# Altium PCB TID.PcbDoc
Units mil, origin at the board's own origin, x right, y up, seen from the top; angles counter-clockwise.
Board outline 1000 x 1330 mil, 4 copper layers (Top Layer, InternalPlane1, MidLayer1, Bottom Layer), stack 88.8 mil thick; 24 components, 7 nets, 51 pads, 63 vias.
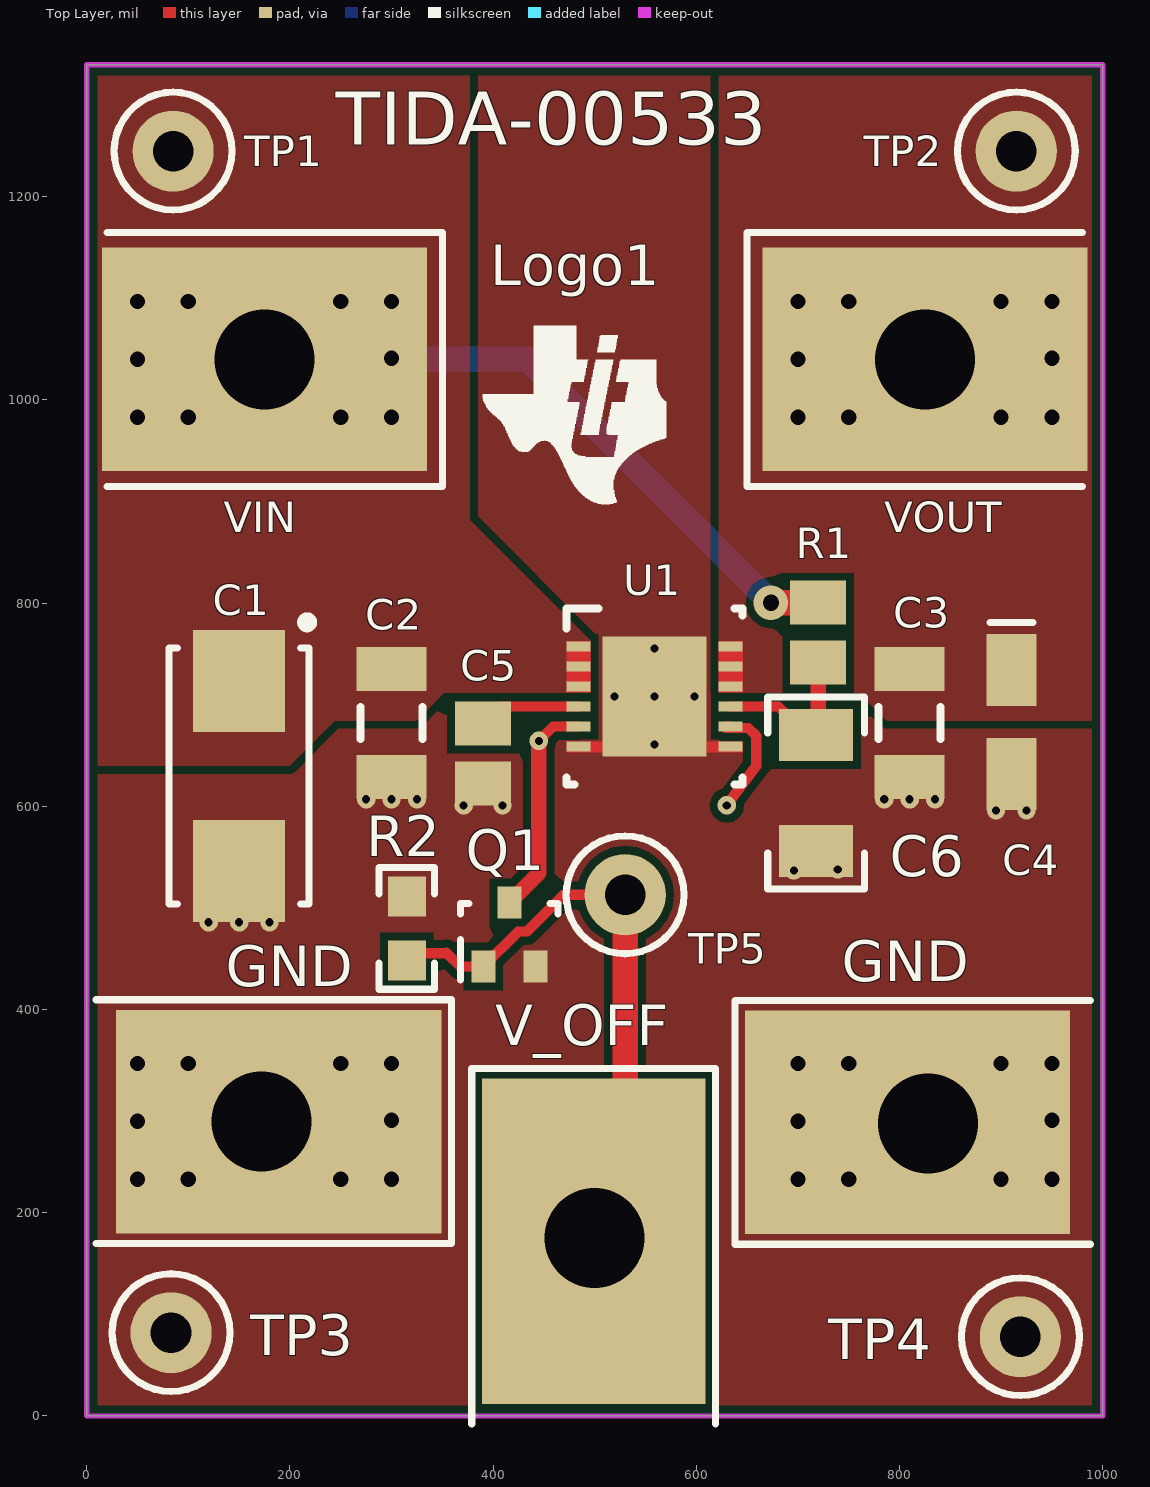
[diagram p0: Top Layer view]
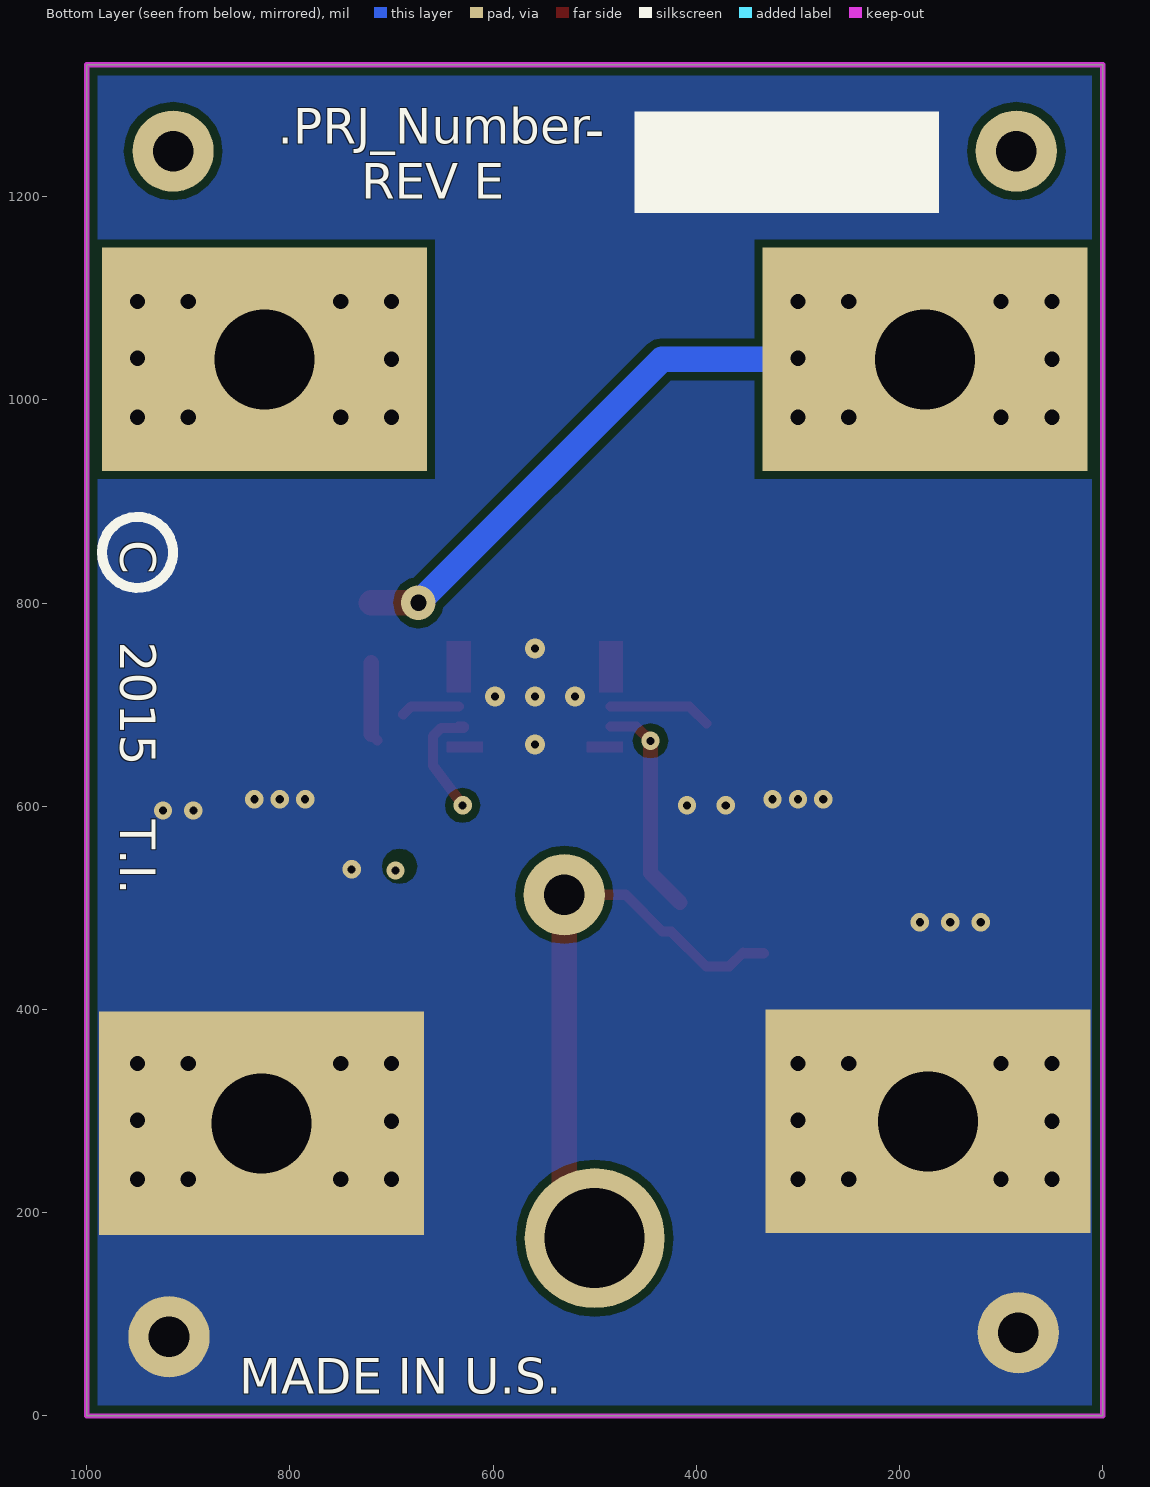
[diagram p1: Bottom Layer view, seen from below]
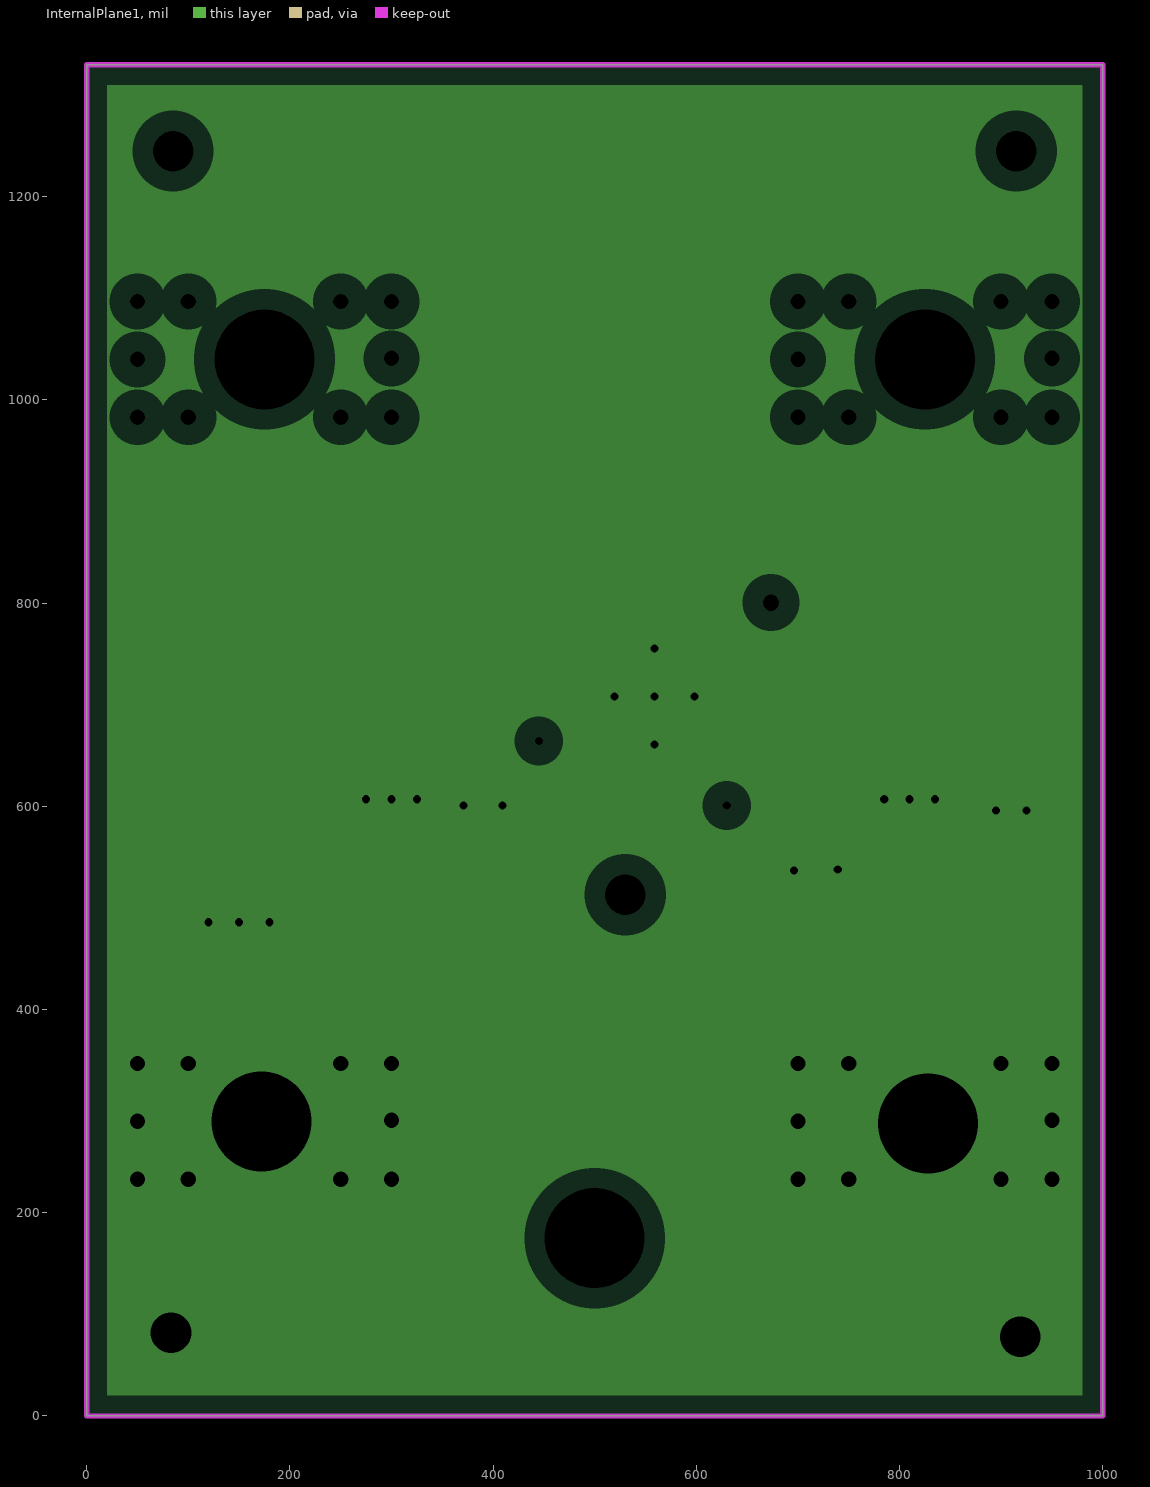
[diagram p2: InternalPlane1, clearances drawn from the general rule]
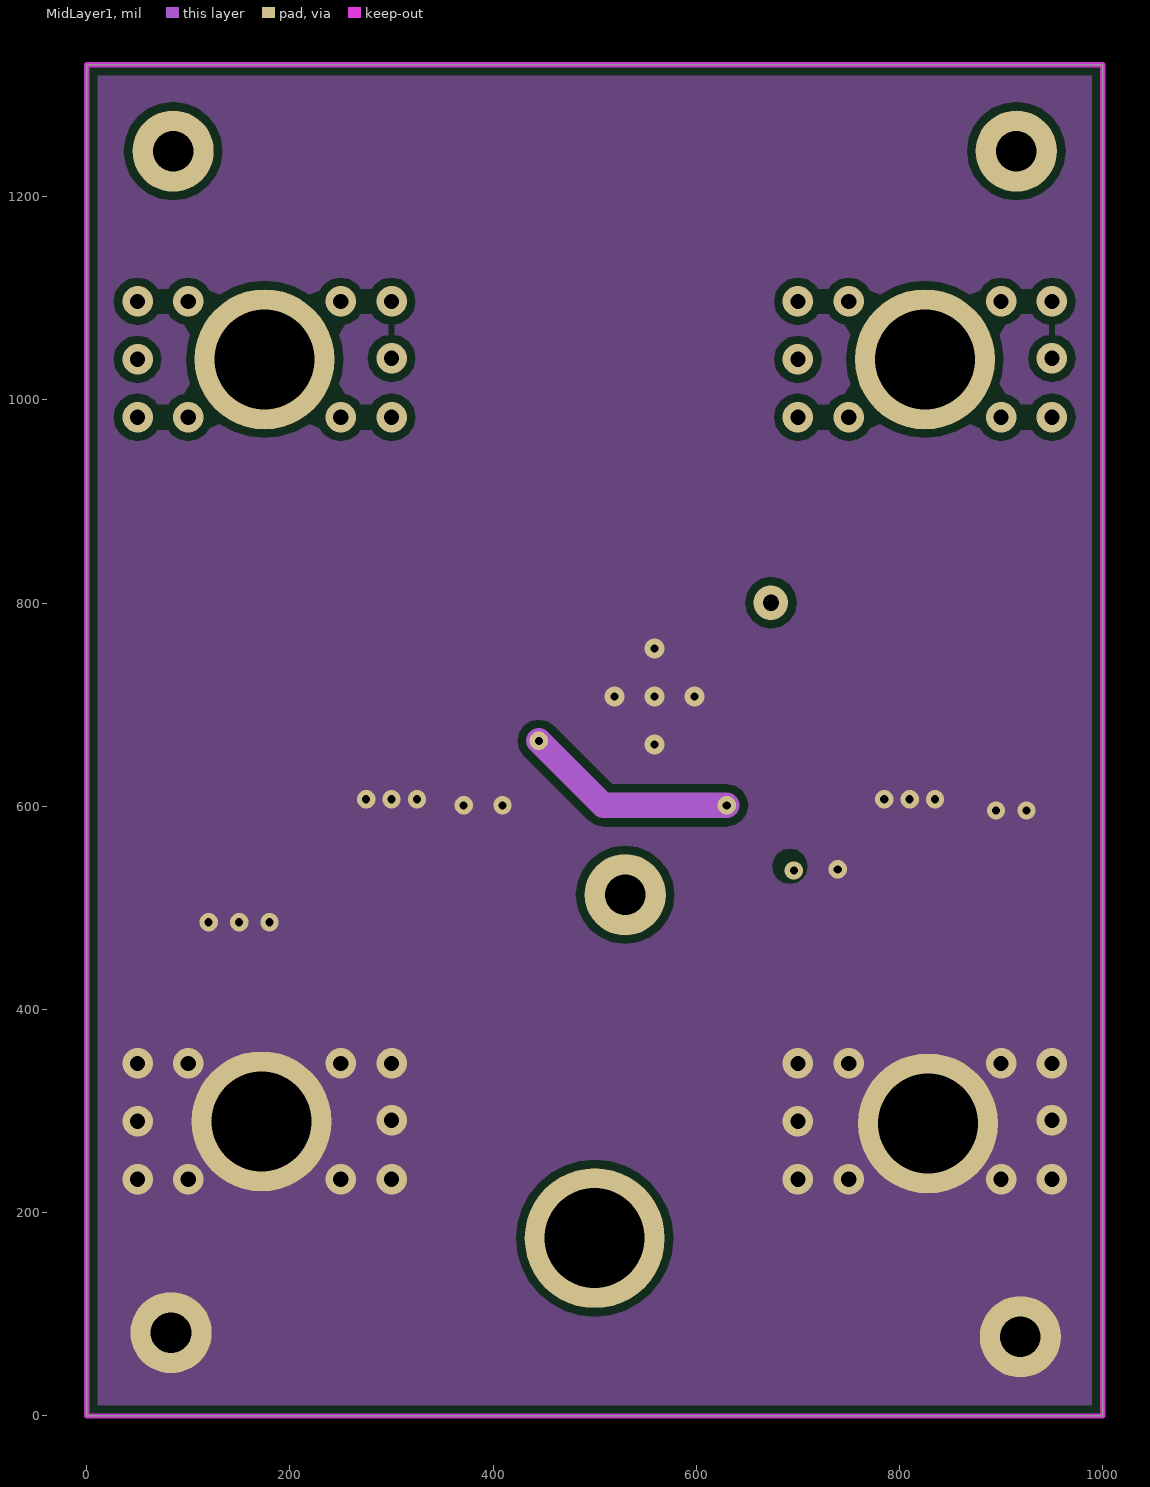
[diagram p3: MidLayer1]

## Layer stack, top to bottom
Top Solder: solder mask 0.4, Solder Resist, Dk 3.5
Top Layer: signal copper 1.4
Dielectric1: core 58, FR-4, Dk 4.8
InternalPlane1: plane copper 1.4, net GND
Dielectric3: prepreg 12.6, FR-4, Dk 4.8
MidLayer1: signal copper 1.4
Dielectric2: core 12.6, FR-4, Dk 4.8
Bottom Layer: signal copper 1.4
Bottom Solder: solder mask 0.4, Solder Resist, Dk 3.5

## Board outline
0,0 1000,0 1000,1330 0,1330

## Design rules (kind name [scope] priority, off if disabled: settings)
AcuteAngle [All] p1: minimum=4.50000000000000E+0001 checktracksonly=FALSE
AssemblyTestPointUsage [All] p1: valid=2
Clearance [All] p1: gap=8
ComponentClearance ComponentClearance_Logo [InComponentClass(Logo)] p1: gap=50 collisioncheckmode=3 verticalgap=10 showdistances=FALSE
ComponentClearance ComponentClearance_ScrewToNut [(HasFootprint('NY PMS 440 0025 PH')) vs (HasFootprint('Keystone_1902C'))] p2: gap=5 collisioncheckmode=3 verticalgap=10 showdistances=FALSE
ComponentClearance ComponentClearance_MountingHoles [InComponentClass('Mounting Holes')] p3: gap=150 collisioncheckmode=3 verticalgap=100000 showdistances=FALSE
ComponentClearance ComponentClearance_SmallPassives [HasFootprint('0201*') or HasFootprint('0402*') or HasFootprint('0508') or HasFootprint('0603*') or HasFootprint('0612') or HasFootprint('0805*') or HasFootprint('0815*') or HasFootprint('0830*') or HasFootprint('1206*') or HasFootprint('1210*') or HasFootprint('1808*') or HasFootprint('1812*') or HasFootprint('1825*') or HasFootprint('2010*') or HasFootprint('2220*') or HasFootprint('2225*') or HasFootprint('2512*') or HasFootprint('2728*') or HasFootprint('3518*') vs HasFootprint('0201*') or HasFootprint('0402*') or HasFootprint('0508') or HasFootprint('0603*') or HasFootprint('0612') or HasFootprint('0805*') or HasFootprint('0815*') or HasFootprint('0830*') or HasFootprint('1206*') or HasFootprint('1210*') or HasFootprint('1808*') or HasFootprint('1812*') or HasFootprint('1825*') or HasFootprint('2010*') or HasFootprint('2220*') or HasFootprint('2225*') or HasFootprint('2512*') or HasFootprint('2728*') or HasFootprint('3518*')] p4: gap=15 collisioncheckmode=3 verticalgap=10 showdistances=FALSE
ComponentClearance ComponentClearance_THtoSMT [IsThruComponent vs IsSMTComponent] p5: gap=20 collisioncheckmode=3 verticalgap=100000 showdistances=FALSE
ComponentClearance ComponentClearance_THtoTH [IsThruComponent vs IsThruComponent] p6: gap=100 collisioncheckmode=3 verticalgap=100000 showdistances=FALSE
ComponentClearance [All] p7: gap=20 collisioncheckmode=3 verticalgap=10 showdistances=FALSE
DiffPairsRouting [All] p1: maxlimit=100 minlimit=10 mostfreqgap=10 toplayer_minwidth=15 toplayer_maxwidth=15 toplayer_prefwidth=15 midlayer1_minwidth=15 midlayer1_maxwidth=15 midlayer1_prefwidth=15 bottomlayer_minwidth=15 bottomlayer_maxwidth=15 bottomlayer_prefwidth=15 maxuncoupledlength=1000
FabricationTestPointUsage TestPointUsage [All] p1: valid=2 allowmultiple=FALSE
FabricationTestpoint Testpoint [All] p1: side=3 testpointundercomponent=TRUE minsize=40 maxsize=100 preferedsize=60 minholesize=0 maxholesize=40 preferedholesize=32 testpointgrid=1 allowsidetop=TRUE allowsidebottom=TRUE usegrid=TRUE gridtolerance=0.01
FanoutControl Fanout_LCC [IsLCC] p1: bgadir=Out bgaviamode=Centered fanoutstyle=Auto fanoutdirection=Alternating viagrid=1 // Fanout_LCC (Default Rule)
FanoutControl Fanout_BGA [IsBGA] p2: bgadir=Out bgaviamode=Centered fanoutstyle=Auto fanoutdirection=Alternating viagrid=1 // Fanout_BGA (Default Rule)
FanoutControl Fanout_Default [All] p4: bgadir=Out bgaviamode=Centered fanoutstyle=Auto fanoutdirection=Alternating viagrid=1 // Fanout_Default (Default Rule)
FanoutControl Fanout_Small [(CompPinCount < 5)] p5: bgadir=Out bgaviamode=Centered fanoutstyle=Auto fanoutdirection=OutThenIn viagrid=1 // Fanout_Small (Default Rule)
HoleSize [All] p1: absolutevalues=TRUE maxlimit=251 minlimit=5 maxpercent=80.000 minpercent=20.000
MinimumAnnularRing [All] p1: minimumring=2
MinimumSolderMaskSliver [All] p1: minsoldermaskwidth=1
PlaneClearance [All] p1: clearance=20
PlaneConnect [All] p1: planeconnectstyle=Direct reliefexpansion=10 reliefentries=4 reliefconductorwidth=10 reliefairgap=10
PolygonConnect [All] p1: connectstyle=Direct reliefconductorwidth=10 reliefentries=4 polygonreliefangle="90 Angle" airgapwidth=10
RoutingLayers [All] p1: top layer_v5=TRUE mid layer 1_v5=FALSE bottom layer_v5=TRUE
RoutingVias [All] p1: holewidth=16 width=34 viastyle="Through Hole" minholewidth=8 minwidth=26 maxholewidth=40 maxwidth=65
SMDToCorner [All] p1: distance=0
SilkToSilkClearance [All] p1: silktosilkclearance=5
SilkToSolderMaskClearance SilkscreenOverComponentPads [IsPad] p1: minsilkscreentomaskgap=2 clearancetoexposedcopper=TRUE
SolderMaskExpansion [All] p1: expansion=3
UnpouredPolygon [All] p1: allowunpoured=FALSE
Width [All] p1: maxlimit=100 minlimit=6 preferedwidth=10 checkconnectedcopper=TRUE
13 further rules are at their usual default settings.

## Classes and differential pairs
component class BlankSheet: C1 C2 C3 C4 C5 C6 GND Q1 R1 R2 TP1 TP2 TP3 TP4 TP5 TP14 TP? U1 V_OFF VIN VOUT
component class Logo: Logo1
component class AssemblyNote: ZZ2 ZZ3 ZZ4
component class TID_Hardware: !PCB Logo1 ZZ2 ZZ3 ZZ4

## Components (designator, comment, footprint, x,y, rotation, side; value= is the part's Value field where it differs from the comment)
C1 "TPSC106K025R0500" 6032-28 150,630 r270 top
C2 "12103C105KAT2A" 1206L 300,682 r270 top
C3 "1206YC106KAT2A" 1206L 810,682 r270 top
C4 "TPSA106K010R0900" 3216-18 910,683 r270 top
C5 "08055C104KAT2A" 0805L 390,652 r270 top
C6 "GRM31CR71C106KAC7L" 1206 718,613 r270 top
GND "6092" 6092 993,289 r180 top
GND "6092" 6092 4,289.64 r0 top
Logo1 "Texas Instruments" TI_Symbol_Overlay_Small 480,985 r0 top
Q1 "2N7002KW" SOT-323 416,474 r90 top
R1 "CRCW080510K0FKEA" 0805L 720,771 r270 top
R2 "RC0603FR-07100KL" 0603 315,480 r270 top
TP1 "5000" Keystone5000 85,1245 r0 top
TP2 "5000" Keystone5000 915,1245 r0 top
TP3 "5001" Keystone5001 83,82 r0 top
TP4 "5001" Keystone5001 919,78 r0 top
TP5 "5002" Keystone5002 529.92,513 r0 top
U1 "LP38798SD-ADJ/NOPB" DNT0012B 559,708 r0 top
V_OFF "6091" 6091#1 499,-13 r90 top
VIN "6091" 6091#2 175,1040 r0 top
VOUT "6091" 6091#2 825,1040 r180 top
ZZ2 "These assemblies are ESD sensitive, ESD precautions shall be observed." AssemblyNote -721,2060 r0 top
ZZ3 "These assemblies must be clean and free from flux and all contaminants. Use of no clean flux is not acceptable." AssemblyNote -721,1693 r0 top
ZZ4 "These assemblies must comply with workmanship standards IPC-A-610 Class 2, unless otherwise specified." AssemblyNote -1048,1532 r0 top

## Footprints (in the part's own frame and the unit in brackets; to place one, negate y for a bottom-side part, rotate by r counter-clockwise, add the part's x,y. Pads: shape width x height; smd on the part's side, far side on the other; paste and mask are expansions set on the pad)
0603 [mm] "0603 from SM-752 data"
  rect 1x0.95 smd: 1(-0.8,0) 2(0.8,0)
  silkscreen extent -1.52,-0.69 1.52,0.69, body extent -0.87,-0.47 0.87,0.47, height 0.85
0805L [mm] "0805 from SM-752 data"
  rect 1.1x1.4 smd: 1(-0.75,0) 2(0.75,0)
  body extent -1.1,-0.72 1.1,0.72, height 1.1
1206 [mm] "1206 from SM-752 data"
  rect 1.3x1.85 smd: 1(-1.45,0) 2(1.45,0)
  silkscreen extent -2.4,-1.21 2.4,1.21, body extent -1.7,-0.9 1.7,0.9, height 1.35
1206L [mm] "1206 from SM-752 data"
  rect 1.1x1.75 smd: 1(-1.35,0) 2(1.35,0)
  silkscreen extent -0.4,-0.78 0.4,0.78, body extent -1.7,-0.9 1.7,0.9, height 1.35
3216-18 [mm] "Medium density IPC, based on Kemet T495 dimensions"
  rect 1.8x1.25 smd: 1(-1.3,0) 2(1.3,0)
  silkscreen extent -2.49,-0.54 -2.49,0.54, body extent -1.7,-0.9 1.7,0.9, height 1.8
6032-28 [mm] "Medium Density IPC based on Vishay Sprague 293D datasheet."
  rect 2.55x2.3 smd: 1(-2.375,0) 2(2.375,0)
  silkscreen extent -3.96,-1.75 3.2,1.83, body extent -3.15,-1.75 3.15,1.75, height 2.8
6091#1 [mil] "Keystone Insulated End Launch Banana Jack"
  rect 320x220 smd: 1(185,0)
  silkscreen extent 5,-120 355,120, body extent -666,-216 271,216, height 227
6091#2 [mil] "Keystone Insulated End Launch Banana Jack"
  rect 320x220 smd: 1(0,0)
  silkscreen extent -155,-125 175,125, body extent -846,-216 91,216, height 227
6092 [mil] "Keystone Insulated End Launch Banana Jack"
  rect 320x220 smd: 1(185,0)
  silkscreen extent 5,-120 355,120, body extent -666,-216 271,216, height 227
AssemblyNote [mil] "Assembly Note"
DNT0012B [mm] "SON, 12-Leads, Body 4x4mm, Pitch 0.5mm"
  rect 0.6x0.25 smd: 1(-1.9,1.25) 2(-1.9,0.75) 3(-1.9,0.25) 4(-1.9,-0.25) 5(-1.9,-0.75) 6(-1.9,-1.25) 7(1.9,-1.25) 8(1.9,-0.75) 9(1.9,-0.25) 10(1.9,0.25) 11(1.9,0.75) 12(1.9,1.25)
  rect 2.6x3 smd paste-1.3: 13(0,0)
  silkscreen extent -2.2,-2.2 2.2,2.2, body extent -2.05,-2.05 2.05,2.05, height 0.81
Keystone5000 [mil] "For Keystone 500x miniature loop terminals"
  round 80 hole 40: 1(0,0)
  silkscreen extent -58,-58 58,58, body extent -49,-49 49,49, height 182
Keystone5001 [mil] "For Keystone 500x miniature loop terminals"
  round 80 hole 40: 1(0,0)
  silkscreen extent -58,-58 58,58, body extent -49,-49 49,49, height 182
Keystone5002 [mil] "For Keystone 500x miniature loop terminals"
  round 80 hole 40: 1(0,0)
  silkscreen extent -58,-58 58,58, body extent -49,-49 49,49, height 182
SOT-323 [mm] "Zetex recommended land pattern.  March 2007"
  rect 0.8x0.6 smd: 1(-0.8,0.65) 2(-0.8,-0.65) 3(0.8,0)
  silkscreen extent -1.14,-1.22 0.77,1.22, body extent -1.13,-1.13 1.12,1.12, height 1.13
TI_Symbol_Overlay_Small [mil]
  silkscreen extent -90,-88 91,88

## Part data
C1: "CAP, TANT, 10uF, 25V, +/-10%, 0.5 ohm, 6032-28 SMD"
C2: library part 12063C105KAT2A, "CAP, MLCC, 1uF, 25V, +/-10%, X7R, 1206"
C3: library part C3216X5R1C106M, "CAP, MLCC, 10uF, 16V, +/-10%, X7R, 1206"
C4: "CAP, TANT, 10uF, 10V, +/-10%, 0.9 ohm, 3216-18 SMD"
C5: "CAP, CERM, 0.1uF, 50V, +/-10%, X7R, 0805"
C6: "CAP, CERM, 10 µF, 16 V, +/- 10%, X7R, 1206"
GND GND: "Standard Banana Jack, Insulated, Black"
Logo1: library part TI_Logo, "Texas Instrument Corporate Signature"
Q1: "MOSFET, N-CH, 60 V, 0.31 A, SOT-323"
R1: "RES, 10.0 k, 1%, 0.125 W, 0805"
R2: "RES, 100 k, 1%, 0.1 W, 0603"
TP1 TP2: "Test Point, TH, Miniature, Red"
TP3 TP4: "Test Point, Miniature, Black, TH"
TP5: "Test Point, TH, Miniature, White"
U1: "Ultra Low Noise, 800 mA Linear Voltage Regulator for RF/Analog Circuits, DNT0012B"
V_OFF VIN VOUT: "Standard Banana Jack, Insulated, Red"
ZZ2 ZZ3 ZZ4: library part AssemblyNote

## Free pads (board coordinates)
  round 137.79 hole 98.42: 0(175,1040) 0(825,1040) 1(500,175) 2(172,290) 3(828,288)
  rect 320x220 smd far side: GND(172,290) GND(828,288) VIN(175,1040) VOUT(825,1040)

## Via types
v1: diameter 30, hole 15, Top Layer to Bottom Layer, tented bottom, 40 vias
v2: diameter 18, hole 8, Top Layer to Bottom Layer, tented both sides, 15 vias
v3: diameter 19.68, hole 7.87, Top Layer to Bottom Layer, 5 vias
v4: diameter 18, hole 8, Top Layer to Bottom Layer, tented bottom, 2 vias
v5: diameter 34, hole 16, Top Layer to Bottom Layer, 1 vias

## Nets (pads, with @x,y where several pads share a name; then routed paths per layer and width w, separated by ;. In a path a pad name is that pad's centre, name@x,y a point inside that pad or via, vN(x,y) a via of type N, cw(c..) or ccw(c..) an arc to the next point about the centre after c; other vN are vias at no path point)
FB_EN: Q1.3 U1.5 U1.8 | length 544.9
  Top Layer w10: v4(445,664.47) 459,678.47 U1.5 ; v4(630,601) 659,640 659,669.38 651.38,677 628.88,677 628.88,678.47 U1.8
  Top Layer w15: Q1.3 445,534.5 v4(445,664.47)
  MidLayer1 w25: v4(445,664.47) 508.47,601 v4(630,601)
GND: C1.2 C2.2 C3.2 C4.2 C5.2 C6.2 GND.1 pad.2 pad.3 pad.GND Q1.2 R2.1 TP3.1 TP4.1 U1.6 U1.7 U1.13
  other v1: 50,233 100,233 250,233 300,233 700,233 750,233 900,233 950,233 50,290 700,290 300,291 950,291 50,347 100,347 250,347 300,347 700,347 750,347 900,347 950,347
  other v2: 120,486 150,486 180,486 696,537 739.24,538 895,596 925,596 371,601 409.25,601 275,607 300,607 325,607 785,607 810,607 835,607
  other v3: 559,660.76 519.63,708 559,708 598.37,708 559,755.24
NetC5_1: C5.1 U1.4 | length 101.1
  Top Layer w10: C5.1 406.63,698.16 U1.4
NetC6_1: C6.1 R1.2 U1.9 | length 136.6
  Top Layer w10: U1.9 680.93,698.16 C6.1@688.41,690.68 ; C6.1@714,665.09 C6.1@720,671.09
  Top Layer w15: C6.1@720,671.09 R1.2
V_OFF: pad.1 Q1.1 R2.2 TP5.1 V_OFF.1 | length 581.6
  Top Layer w10: 333.7,455.5 353.5,455.5 354,456 367.5,442.5 Q1.1 424.65,476.75 433.2,476.75 469.45,513 TP5.1 ; pad.1 pad.1@529.92,204.92
  Top Layer w25: pad.1@529.92,204.92 TP5.1
VIN: C1.1 C2.1 pad.0@175,1040 pad.VIN R1.1 TP1.1 U1.1 U1.2 U1.3 VIN.1 | length 644.2
  Top Layer w25: v5(673.47,800.53) R1.1
  Bottom Layer w25: pad.VIN 434,1040 v5(673.47,800.53)
  other v1: 50,983 100,983 250,983 300,983 50,1040 300,1041 50,1097 100,1097 250,1097 300,1097
VOUT: C3.1 C4.1 pad.0@825,1040 pad.VOUT TP2.1 U1.10 U1.11 U1.12 VOUT.1
  other v1: 700,983 750,983 900,983 950,983 700,1040 950,1041 700,1097 750,1097 900,1097 950,1097

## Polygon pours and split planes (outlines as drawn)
VOUT on Top Layer "Top Layer-No Net 1" (solid, pour order 4): 622,712 760,712 787.62,684.38 1000,684.38 1000,1330 622,1330
VIN on Top Layer "Top Layer-No Net" (solid, pour order 2): 496,712 352,712 324.38,684.38 244.38,684.38 200,640 0,640 0,1330 377,1329 377,882 496,763
GND on Top Layer "Top Layer-No Net 2" (solid, pour order 13): 0,0 1000,0 1000,1330 999,1328.97 0,1328.97 0,1330
GND on Bottom Layer "Bottom Layer-No Net" (solid, pour order 9): 0,0 1000,0 1000,1330 0,1330
GND on MidLayer1 "MidLayer1-No Net" (solid, pour order 11): 0,0 1000,0 1000,1330 0,1330
GND on InternalPlane1 (split plane): 979.9,20.1 20.1,20.1 20.1,1309.9 979.9,1309.9

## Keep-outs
Keep-Out Layer:
  the board outline again, w5
  text ".Layer_Name" at -1023,-1518.49 h60

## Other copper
Top Layer:
  rectangle net VOUT: 622,712 646,763
  rectangle net VIN: 472,712 496,763
  rectangle net GND: 610,653 646,664
  region net GND: 508,664 472,664 472,653 508,653
  text ".Layer_Name" at -1023,-1518.49 h60
Bottom Layer:
  text ".Layer_Name" at -1023,-1518.49 h60

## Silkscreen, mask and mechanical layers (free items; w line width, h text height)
Top Overlay:
  text "TIDA-00533" at 245,1234 h90
  text ".Layer_Name" at -1023,-1518.49 h60
Bottom Overlay:
  circle w10: c950,850 r35
  rectangle: 161,1184 461,1284
  text ".PRJ_Number" at 812,1252 h35
  text "-" at 490,1247 h40
  text "REV E" at 730,1198 h35
  text "C" at 967,862 h35 r90
  text "2015" at 967,762 h35 r90
  text "T.I." at 967,587 h35 r90
  text "MADE IN U.S." at 850,22 h35
  text ".Layer_Name" at -1023,-1518.49 h60
Top Paste:
  text ".Layer_Name" at -1023,-1518.49 h60
Bottom Paste:
  text ".Layer_Name" at -1023,-1518.49 h60
Top Solder:
  text ".Layer_Name" at -1023,-1518.49 h60
  text ".Layer_Name" at -1023,-1518.49 h60
Bottom Solder:
  text ".Layer_Name" at -1023,-1518.49 h60
Drill Guide:
  text ".Layer_Name" at -1023,-1518.49 h60
M1 Board Outline:
  the board outline again, w5
  text ".Layer_Name" at -1023,-1518.49 h60
M2 Board Dimensions:
  rectangle: -1600.5,-945.5 -1475.5,-820.5
  rectangle: -1475.5,-1070.5 -1100.5,-945.5
  lines w7: -1600.5,-945.5 -600.5,-945.5 ; -1475.5,-1070.5 -1475.5,-820.5 ; -1350.5,-1070.5 -1350.5,-820.5 ; -1100.5,-1070.5 -1100.5,-820.5 ; -850.5,-1070.5 -850.5,-820.5 ; -1600.5,-1070.5 -600.5,-1070.5 -600.5,-820.5 -1600.5,-820.5 -1600.5,-1070.5
  lines w10: -1600.5,-1135.5 -1600.5,-1115.5 ; -1540.5,-1145.5 -1600.5,-1125.5 ; -1540.5,-1105.5 -1600.5,-1125.5 ; -1376.42,-1125.5 -1600.5,-1125.5 ; -824.58,-1125.5 -600.5,-1125.5 ; -660.5,-1145.5 -600.5,-1125.5 ; -660.5,-1105.5 -600.5,-1125.5 ; -600.5,-1135.5 -600.5,-1115.5
  text "1000 (mil)" at -1366.42,-1161.49 h60
  text ".Layer_Name" at -1023,-1518.49 h60
M3 3D STEP Top:
  text ".Layer_Name" at -1023,-1518.49 h60
M4 3D STEP Bottom:
  text ".Layer_Name" at -1023,-1518.49 h60
M5 Assembly Top:
  lines w7: 7740,-623.5 8865,-623.5 ; 7740,-501 8862.5,-501 ; 8055,-743.5 8055,-381 ; 8440,-743.5 7740,-743.5 ; 8440,-381 7740,-381 ; 7740,-743.5 8865,-743.5 8865,-381 7740,-381 ; 7740,-743.5 7740,-381
  lines w10: -1892,-1590.17 4708,-1590.17 ; -1892,-1386.83 4710,-1386.83 ; -1892,-1183.5 -1892,-1793.5 2113,-1793.5 4710,-1793.5 4710,-1183.5 -1891.5,-1183.5 -1891.5,-1793.5 -316,-1793.5 ; 573,-1793.5 573,-1183.5 ; 1840,-1386.83 1840,-1183.5 ; 2680,-1386.83 2680,-1183.5 ; 3302,-1800 3302,-1597.17
  text "TABLE 1" at 8127.5,-346 h40
  text "Variant" at 7765,-456 h40
  text "Label text" at 8200,-456 h40
  text "001" at 7832.5,-576 h40
  text "TIDA-00533" at 8110,-578.5 h40
  text "COMPONENTS MARKED 'DNP' SHOULD NOT BE POPULATED, AND MAY NOT BE IN BILL OF MATERIALS" at -446.5,-978.5 h60
  text "ASSEMBLY VARIANT:" at -447,-1094 h60
  text ".VariantName" at 589,-1094 h60
  text "PCB VIEWED FROM TOP SIDE" at -1828.5,-1315.67 h60
  text "BOARD #:" at 648,-1315.67 h60
  text ".PRJ_Number" at 1193.5,-1315.67 h60
  text "REV:" at 2038,-1315.67 h60
  text ".PCB_Rev" at 2329.5,-1315.67 h60
  text "SVN REV:" at 2876,-1315.67 h60
  text ".VersionControl_RevNumber" at 3382,-1315.67 h60
  text "IGNORE ->" at -1828.5,-1518.49 h60
  text "PLOT NAME =" at -1828.5,-1724.34 h60
  text ".plot_File_Name" at -1023,-1724.34 h60
  text "GENERATED    :" at 650,-1724.34 h60
  text ".Print_Date" at 1519.5,-1724.34 h60
  text ".Print_Time" at 2248.5,-1724.34 h60
  text "TEXAS INSTRUMENTS" at 3513,-1724.34 h60
M6 Assembly Bottom:
  lines w10: -1892.5,-1387.33 4709.5,-1387.33 ; -1890.5,-1590.67 4709.5,-1590.67 ; -484.5,-1800.5 -484.5,-1597.67 ; 137.5,-1387.33 137.5,-1184 ; 977.5,-1387.33 977.5,-1184 ; 2244.5,-1794 2244.5,-1184 ; 3133.5,-1794 4709,-1794 4709,-1184 -1892.5,-1184 -1892.5,-1794 704.5,-1794 4709.5,-1794 4709.5,-1184
  text "COMPONENTS MARKED 'DNP' SHOULD NOT BE POPULATED, AND MAY NOT BE IN BILL OF MATERIALS" at 4502,-978 h60
  text ".VariantName" at 3458,-1094 h60
  text "ASSEMBLY VARIANT:" at 4497,-1094 h60
  text ".VersionControl_RevNumber" at -564.5,-1316.17 h60
  text "SVN REV:" at -58.5,-1316.17 h60
  text ".PCB_Rev" at 488,-1316.17 h60
  text "REV:" at 779.5,-1316.17 h60
  text ".PRJ_Number" at 1624,-1316.17 h60
  text "BOARD #:" at 2169.5,-1316.17 h60
  text "PCB VIEWED FROM BOTTOM SIDE" at 4646,-1316.17 h60
  text "IGNORE ->" at 947.85,-1518.49 h60
  text "TEXAS INSTRUMENTS" at -695.5,-1724.84 h60
  text ".Print_Time" at 569,-1724.84 h60
  text ".Print_Date" at 1298,-1724.84 h60
  text "GENERATED    :" at 2167.5,-1724.84 h60
  text ".plot_File_Name" at 3840.5,-1724.84 h60
  text "PLOT NAME =" at 4646,-1724.84 h60
M9 Title Sheet:
  drawing of 57 lines, arcs and shapes, not listed
  text "1" at -860.16,7376.5 h70
  text "2" at 1635.5,7376.5 h70
  text "3" at 4124.84,7376.5 h70
  text "4" at 6631.51,7376.5 h70
  text "5" at 9130.5,7376.5 h70
  text "6" at 11635.5,7376.5 h70
  text "A" at -2016.5,6233.5 h70
  text "A" at 12783.5,6233.5 h70
  text "B" at -2016.5,3853.5 h70
  text "B" at 12783.5,3853.5 h70
  text "C" at -2016.5,1478.5 h70
  text "C" at 12783.5,1478.5 h70
  text "PROJECT TITLE:" at 9743.5,-382.5 h45
  text ".PRJ_Title" at 9793.5,-515.83 h70
  text "DESIGNED FOR:" at 9743.5,-683.5 h45
  text ".PRJ_Customer" at 9793.5,-823.5 h70
  text "D" at -2016.5,-891.5 h70
  text "D" at 12783.5,-891.5 h70
  text "FILE NAME:" at 9743.5,-983.5 h45
  text ".PCB_File_Name_No_Path" at 9793.5,-1103.5 h70
  text "Texas Instruments (TI) and/or its licensors do not warrant the accuracy or completeness of this specification" at 4774,-1265.34 h45
  text "ENGINEER:" at 9743.5,-1273.5 h45
  text "LAYOUT BY:" at 11248.5,-1273.5 h45
  text "or any information contained therein. TI and/or its licensors do not warrant that this design will meet" at 4729.01,-1378 h45
  text ".PRJ_Engineer" at 9793.5,-1428.49 h70
  text ".PCB_Layout" at 11299,-1428.49 h70
  text "the specifications, will be suitable for your application or fit for any particular purpose, or will operate in" at 4729.01,-1490.67 h45
  text ".Layer_Name" at -1023,-1518.49 h60
  text "ALTIUM DESIGNER VERSION:" at 11248.5,-1583.5 h45
  text "an implementation. TI and/or its licensors do not warrant that the design is production worthy. You should" at 4729.01,-1603.33 h45
  text "completely validate and test your design implementation to confirm the system functionality for your application." at 4774,-1716 h45
  text ".print_Scale" at 9793.5,-1716.83 h70
  text ".Application_BuildNumber" at 11299,-1716.83 h70
  text "1" at -860.16,-1923.5 h70
  text "2" at 1635.5,-1923.5 h70
  text "3" at 4124.84,-1923.5 h70
  text "4" at 6631.51,-1923.5 h70
  text "5" at 9130.5,-1923.5 h70
  text "6" at 11635.5,-1923.5 h70
M10 Fab Notes:
  drawing of 207 lines, arcs and shapes, not listed
  text "DESIGN INFORMATION" at 10728.02,6223 h60
  text "(REFER ALSO ARRAY/PANEL PROFILING INFORMATION)" at 10366.46,6061.29 h60
  text "BOARD SIZE" at 9680.46,6057 h60
  text "1330MIL" at 10142.78,5929.18 h60
  text "X" at 10648.46,5929.18 h60
  text "1000MIL" at 10879.78,5929.18 h60
  text "Number of Layers :" at 10083.46,5732 h60
  text "4" at 11178.27,5722 h60
  text "MIN. TRACK WIDTH:" at 10083.46,5593 h60
  text "10" at 11179.7,5593 h60
  text "MIL" at 11334.46,5593 h60
  text "MIN. CLEARANCE:" at 10083.46,5461 h60
  text "8" at 11179.7,5461 h60
  text "MIL" at 11334.46,5461 h60
  text "MIN. VIA PAD SIZE:" at 10083.46,5329 h60
  text "10" at 11149.71,5329 h60
  text "MIL" at 11334.46,5329 h60
  text "0.05mm (2MIL)" at 10778.46,5187.29 h60
  text "MINIMUM ANNULAR RING" at 9754.23,5183 h60
  text "EXTERNAL" at 11486.46,5183 h60
  text "PER" at 9954.23,5065 h60
  text "IPC-D-275 CLASS 2 LEVEL C" at 10174.23,5065 h60
  text "MIL, HOLES" at 11662.46,4952.71 h60
  text "+/-" at 11270,4952 h60
  text "+/-" at 12124,4952 h60
  text "REGISTRATION TOLERANCES:" at 9754.23,4947 h60
  text "METAL" at 10954,4947 h60
  text "5" at 11530.2,4947 h60
  text "3" at 12363.2,4947 h60
  text "MIL" at 12479.46,4947 h60
  text "MATERIAL:" at 9679.46,4737.54 h60
  text "FR-4 High Tg" at 10665.9,4597.21 h60
  text "X" at 10512,4593 h60
  text "FR-4" at 10140.46,4588.64 h60
  text "OTHER" at 11588.46,4588.64 h60
  text "62 MIL (1.6mm) +/-10%" at 10420.56,4425.92 h60
  text "THICKNESS:" at 9754.23,4421.64 h60
  text "X" at 10292.4,4421.64 h60
  text "OTHER" at 11705.46,4421.64 h60
  text "TOLERANCE:" at 9754.23,4263.64 h60
  text "X" at 10593.53,4263.64 h60
  text "ANSI IPC-6012 TYPE 3 CLASS 2" at 10780.48,4263.64 h60
  text "OTHER +/-" at 10780.46,4107.64 h60
  text "BOW & TWIST:" at 9754.23,3950.64 h60
  text "X" at 10593.53,3950.64 h60
  text "ANSI IPC-6012 TYPE 3 CLASS 2" at 10780.48,3950.64 h60
  text "OTHER +/-" at 10780.46,3792.13 h60
  text "COPPER THICKNESS (FINISHED):" at 9679.46,3656.64 h60
  text "1.4MIL (1oz)" at 10559.46,3503.92 h60
  text "2MIL (1.4oz)" at 11326.46,3503.92 h60
  text "2.8MIL (2oz)" at 12053.46,3503.92 h60
  text "X" at 10425,3503 h60
  text "OUTER:" at 10036.46,3499.64 h60
  text "0.7MIL (0.5oz)" at 10559.46,3345.92 h60
  text "1.4MIL (1oz)" at 11326.46,3339.92 h60
  text "INNER SIGNAL:" at 9743,3334 h60
  text "X" at 11197,3332 h60
  text "2.8MIL (2oz)" at 12059,3331 h60
  text "DRILLING:" at 9679.46,3203.64 h60
  text "REFERENCE:" at 9754.23,3086.64 h60
  text "X" at 10402.46,3086.64 h60
  text "AS SHOWN" at 10589.46,3086.64 h60
  text "X" at 11303.46,3086.64 h60
  text "NC_DRILL FILES" at 11440.46,3086.64 h60
  text "PTH MIN COPPER THICKNESS:" at 9754.23,2928.64 h60
  text "X" at 11104.46,2928.64 h60
  text "1MIL" at 11241.46,2928.64 h60
  text "OTHER" at 11738.46,2928.64 h60
  text "BOARD FINISH:" at 9679.46,2769.64 h60
  text "SILKSCREEN:" at 9834.68,2651.64 h60
  text "X" at 10783.46,2651.64 h60
  text "TOP" at 10909.46,2651.64 h60
  text "X" at 11293.46,2651.64 h60
  text "BOTTOM" at 11420.46,2651.64 h60
  text "SILKSCREEN COLOR:" at 9834.68,2484.64 h60
  text "X" at 10782.42,2484.64 h60
  text "WHITE" at 10909.46,2484.64 h60
  text "OTHER" at 11420.46,2484.64 h60
  text "SOLDER RESIST COLOR:" at 9834.68,2314.64 h60
  text "X" at 10405,2156 h60
  text "GREEN" at 10529.46,2155.44 h60
  text "BLUE" at 11120.46,2155.44 h60
  text "OTHER" at 11658.46,2155.44 h60
  text "IMMERSION GOLD (ENIG)" at 10740.46,1966.92 h60
  text "SURFACE FINISH:" at 9679.46,1962.64 h60
  text "X" at 10553.51,1962.64 h60
  text "Pb-FREE HASL" at 11972.75,1962.64 h60
  text "OTHER" at 10740.46,1805.64 h60
  text "ARRAY/PANEL:" at 9679.46,1626.64 h60
  text "X" at 10554,1623 h60
  text "CUT AND TRIM PER MECH LAYER 1" at 10740.46,1622.35 h60
  text "N.C. ROUTE" at 10740.46,1470.64 h60
  text "V. SCORE" at 11606.46,1470.64 h60
  text "CERTIFICATION:" at 9679.46,1333.64 h60
  text "MATERIALS AND WORKMANSHIP FOR ALL PCBS" at 10404.46,1333.64 h60
  text "TO MEET OR EXCEED THE REQUIREMENTS OF:" at 10404.46,1235.64 h60
  text "X" at 10030.96,1099.13 h60
  text "ANSI IPC-A-600F CLASS ->" at 10169.96,1099.13 h60
  text "X" at 11809.02,1099.13 h60
  text "2" at 11927.96,1099.14 h60
  text "1" at 11612.96,1097.64 h60
  text "3" at 12281.96,1097.64 h60
  text "X" at 10033.02,939.64 h60
  text "UL 94V-0" at 10169.96,939.64 h60
  text "X" at 10845.02,939.64 h60
  text "RoHS" at 10981.96,939.64 h60
  text "OTHER" at 11626.36,939.64 h60
  text "PER ORDER" at 12023.42,939.64 h60
  text "ADDITIONAL REQUIREMENTS:" at 9679.46,798.64 h60
  text "MICROSECTION:" at 9754.23,683.64 h60
  text "YES" at 10659.96,683.64 h60
  text "REQUIRED" at 11521.46,527.49 h60
  text "BARE BOARD ELEC. TEST:" at 9754.23,524.64 h60
  text "NONE" at 11059.96,524.64 h60
  text "X" at 11394.46,524.64 h60
  text "PER ORDER" at 12113.46,524.64 h60
  text "MANUFACTURER'S ID/LOGO:" at 9754.23,367.64 h60
  text "RAIL" at 11219.96,363.35 h60
  text "METAL" at 11711.77,363.35 h60
  text "X" at 12088,363 h60
  text "SILK" at 12223.46,363.35 h60
  text ".Layer_Name" at -1023,-1518.49 h60
M11 Gerber Information:
  lines w10: -1892,-1590.17 4708,-1590.17 ; -1892,-1386.83 4710,-1386.83 ; -1892,-1183.5 -1892,-1793.5 2113,-1793.5 4710,-1793.5 4710,-1183.5 -1891.5,-1183.5 -1891.5,-1793.5 -316,-1793.5 ; 573,-1793.5 573,-1183.5 ; 1840,-1386.83 1840,-1183.5 ; 2680,-1386.83 2680,-1183.5 ; 3302,-1800 3302,-1597.17
  text "ALL ARTWORK VIEWED FROM TOP SIDE" at -1828.5,-1315.67 h60
  text "BOARD #:" at 648,-1315.67 h60
  text ".PRJ_Number" at 1193.5,-1315.67 h60
  text "REV:" at 2038,-1315.67 h60
  text ".PCB_Rev" at 2329.5,-1315.67 h60
  text "SVN REV:" at 2876,-1315.67 h60
  text ".VersionControl_RevNumber" at 3382,-1315.67 h60
  text "LAYER NAME =" at -1828.5,-1518.49 h60
  text "PLOT NAME =" at -1828.5,-1724.34 h60
  text ".plot_File_Name" at -1023,-1724.34 h60
  text "GENERATED    :" at 650,-1724.34 h60
  text ".Print_Date" at 1519.5,-1724.34 h60
  text ".Print_Time" at 2248.5,-1724.34 h60
  text "TEXAS INSTRUMENTS" at 3513,-1724.34 h60
M12 Stackup:
  lines w15: -343,4172 4332,4172 ; -343,4449.4 4332,4449.4 ; -403,2339 ccw(c-313,2339) -313,2249 4302,2249 ccw(c4302,2339) 4392,2339 4392,4713 ccw(c4302,4713) 4302,4803 -313,4803 ccw(c-313,4713) -403,4713 -403,2339
  text "Layer Stack Up Detail for: SV600865A.PcbDoc" at -343,4548.9 h106
  text "Layer" at -343,4345.9 h64
  text "Gerber" at 1334.84,4345.9 h64
  text "Copper" at 2140.83,4345.9 h64
  text "Dielectric" at 3051.31,4345.9 h64
  text "Name" at -343,4217.9 h64
  text "Document" at 1334.84,4217.9 h64
  text "Thickness" at 2140.83,4217.9 h64
  text "Material" at 3051.31,4217.9 h64
  text "Top Solder Mask" at -343,4021.54 h90
  text "(.GTS)" at 1334.84,4021.54 h90
  text "Solder Resist" at 3051.31,4021.54 h90
  text "Top Layer" at -343,3735.63 h90
  text "(.GTL)" at 1334.84,3735.63 h90
  text "1.4mil" at 2140.83,3735.63 h90
  text "FR-4" at 3051.31,3592.67 h90
  text "InternalPlane1" at -343,3449.71 h90
  text "(.GP1)" at 1334.84,3449.71 h90
  text "1.4mil" at 2140.83,3449.71 h90
  text "FR-4" at 3051.31,3306.75 h90
  text "MidLayer1" at -343,3163.79 h90
  text "(.G1)" at 1334.84,3163.79 h90
  text "1.4mil" at 2140.83,3163.79 h90
  text "FR-4" at 3051.31,3020.83 h90
  text "Bottom Layer" at -343,2877.88 h90
  text "(.GBL)" at 1334.84,2877.88 h90
  text "1.4mil" at 2140.83,2877.88 h90
  text "Bottom Solder Mask" at -343,2591.96 h90
  text "(.GBS)" at 1334.84,2591.96 h90
  text "Solder Resist" at 3051.31,2591.96 h90
  text ".Layer_Name" at -1023,-1518.49 h60
M13 Component Bodies Top:
  text ".Layer_Name" at -1023,-1518.49 h60
M14 Component Bodies Bottom:
  text ".Layer_Name" at -1023,-1518.49 h60
M15 Courtyards Top:
  text ".Layer_Name" at -1023,-1518.49 h60
M16 Courtyards Bottom:
  text ".Layer_Name" at -1023,-1518.49 h60
Drill Drawing:
  text ".legend" at 2657,-269 h60
  text "Drill Table" at 2651,-524 h60
  text ".Layer_Name" at -1023,-1518.49 h60

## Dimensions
0,0 to 0,1330 on M2 Board Dimensions
0,0 to 1000,0 on M2 Board Dimensions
